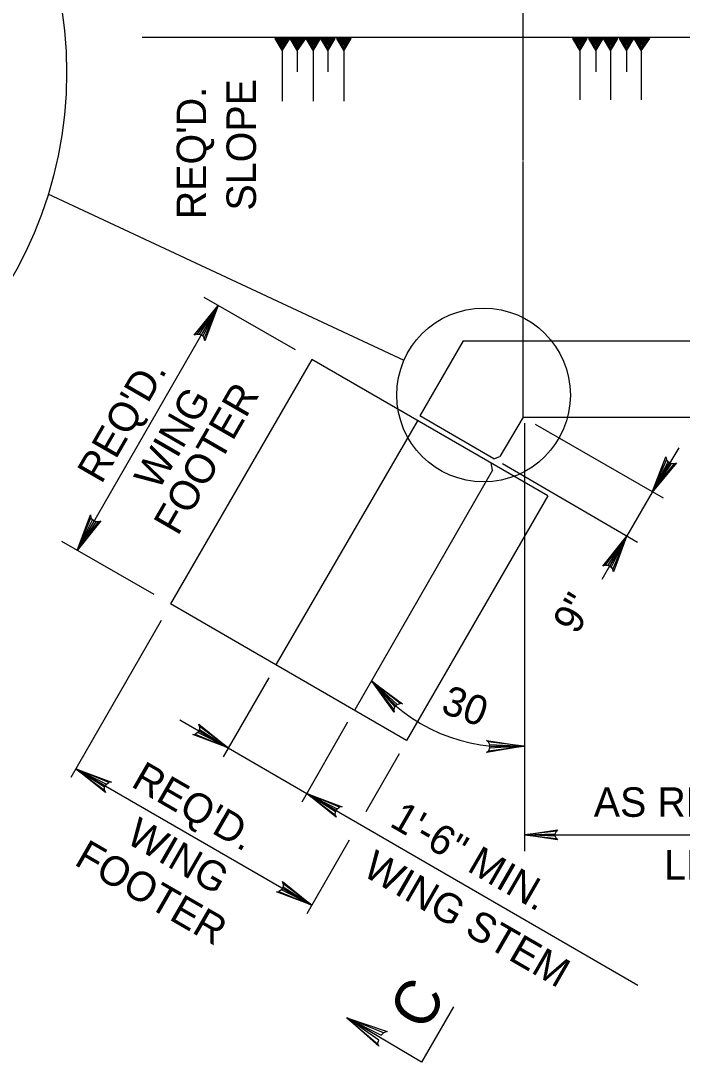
# Model space of a CAD drawing. Extents: x 639011 to 639866, y 298840 to 300028.
# Drawn here: x 639141.6 to 639208.9, y 299864.4 to 299970.3 of the extents above; entities that cross this region are included whole.
import ezdxf

# ---------------------------------------------------------------- set-up
doc = ezdxf.new("R2010")
doc.units = 0
doc.layers.add('2', color=7, linetype='Continuous')

msp = doc.modelspace()

# ---------------------------------------------------------------- linework, layer by layer
at = {"layer": '2'}
for p, q in [((639192.69, 299956.09), (639192.69, 299976.73)), ((639153.94, 299968.6), (639239.07, 299968.6)), ((639164.42, 299968.6), (639305.62, 299968.6)), ((639168.19, 299967.23), (639168.19, 299962.1)), ((639169.69, 299967.23), (639169.69, 299965.1)), ((639171.32, 299967.23), (639171.32, 299962.1)), ((639172.82, 299967.23), (639172.82, 299965.1)), ((639174.44, 299967.23), (639174.44, 299962.1)), ((639198.44, 299967.23), (639198.44, 299962.23)), ((639200.07, 299967.23), (639200.07, 299965.1)), ((639201.57, 299967.23), (639201.57, 299962.23)), ((639203.19, 299967.23), (639203.19, 299965.1)), ((639204.69, 299967.23), (639204.69, 299962.23)), ((639192.69, 299937.23), (639192.69, 299955.98)), ((639180.57, 299935.73), (639144.39, 299952.65)), ((639192.69, 299938.23), (639192.69, 299946.48)), ((639192.69, 299938.23), (639192.69, 299946.48)), ((639169.52, 299936.81), (639160.23, 299942.15)), ((639161.65, 299941.34), (639147.34, 299916.43)), ((639159.24, 299938.33), (639161.65, 299941.34)), ((639161.65, 299941.34), (639159.48, 299938.42)), ((639159.77, 299938.41), (639161.65, 299941.34)), ((639161.65, 299941.34), (639159.93, 299938.32)), ((639161.65, 299941.34), (639160.09, 299938.23)), ((639160.25, 299937.99), (639161.65, 299941.34)), ((639161.65, 299941.34), (639160.31, 299937.73)), ((639159.48, 299938.42), (639159.24, 299938.33)), ((639159.48, 299938.42), (639159.77, 299938.41)), ((639159.77, 299938.41), (639160.09, 299938.23)), ((639160.09, 299938.23), (639160.25, 299937.99)), ((639160.31, 299937.73), (639160.25, 299937.99)), ((639186.57, 299937.73), (639182.19, 299930.1)), ((639186.57, 299937.73), (639244.22, 299937.73)), ((639192.69, 299929.98), (639192.69, 299937.23)), ((639192.69, 299929.98), (639192.69, 299937.23)), ((639171.19, 299935.85), (639156.82, 299910.98)), ((639195.19, 299921.98), (639171.19, 299935.85)), ((639189.69, 299925.73), (639182.19, 299930.1)), ((639181.94, 299929.6), (639167.57, 299904.85)), ((639192.69, 299929.98), (639190.32, 299925.98)), ((639192.69, 299929.98), (639238.07, 299929.98)), ((639192.82, 299929.35), (639192.82, 299885.85)), ((639206.94, 299921.73), (639193.94, 299929.23)), ((639189.69, 299925.73), (639190.32, 299925.98)), ((639208.5, 299926.87), (639205.82, 299922.35)), ((639205.82, 299922.35), (639207.21, 299925.94)), ((639207.21, 299925.94), (639207.26, 299925.68)), ((639189.57, 299924.6), (639189.44, 299925.35)), ((639204.32, 299917.23), (639190.57, 299925.23)), ((639207.26, 299925.68), (639205.82, 299922.35)), ((639205.82, 299922.35), (639207.42, 299925.44)), ((639205.82, 299922.35), (639207.58, 299925.35)), ((639208.27, 299925.32), (639205.82, 299922.35)), ((639207.74, 299925.25), (639205.82, 299922.35)), ((639205.82, 299922.35), (639208.03, 299925.24)), ((639207.42, 299925.44), (639207.26, 299925.68)), ((639207.74, 299925.25), (639207.42, 299925.44)), ((639208.03, 299925.24), (639207.74, 299925.25)), ((639208.03, 299925.24), (639208.27, 299925.32)), ((639189.57, 299924.6), (639175.57, 299900.23)), ((639195.19, 299921.98), (639180.82, 299897.1)), ((639205.82, 299922.35), (639203.19, 299917.85)), ((639147.34, 299916.43), (639148.68, 299920.03)), ((639148.73, 299919.77), (639147.34, 299916.43)), ((639147.34, 299916.43), (639148.89, 299919.53)), ((639148.68, 299920.03), (639148.73, 299919.77)), ((639148.89, 299919.53), (639148.73, 299919.77)), ((639149.21, 299919.35), (639148.89, 299919.53)), ((639147.34, 299916.43), (639149.05, 299919.44)), ((639149.74, 299919.43), (639147.34, 299916.43)), ((639149.21, 299919.35), (639147.34, 299916.43)), ((639147.34, 299916.43), (639149.51, 299919.34)), ((639149.51, 299919.34), (639149.21, 299919.35)), ((639149.51, 299919.34), (639149.74, 299919.43)), ((639203.19, 299917.85), (639200.69, 299913.48)), ((639200.8, 299914.84), (639203.19, 299917.85)), ((639203.19, 299917.85), (639201.03, 299914.93)), ((639201.33, 299914.92), (639203.19, 299917.85)), ((639203.19, 299917.85), (639201.49, 299914.83)), ((639203.19, 299917.85), (639201.64, 299914.74)), ((639201.81, 299914.5), (639203.19, 299917.85)), ((639203.19, 299917.85), (639201.86, 299914.24)), ((639155.15, 299911.93), (639145.75, 299917.33)), ((639201.03, 299914.93), (639200.8, 299914.84)), ((639201.03, 299914.93), (639201.33, 299914.92)), ((639201.33, 299914.92), (639201.64, 299914.74)), ((639201.64, 299914.74), (639201.81, 299914.5)), ((639201.86, 299914.24), (639201.81, 299914.5)), ((639180.82, 299897.1), (639156.82, 299910.98)), ((639155.86, 299909.31), (639146.69, 299893.35)), ((639166.82, 299903.48), (639162.16, 299895.44)), ((639179.63, 299900.51), (639177.31, 299903.1)), ((639177.31, 299903.1), (639179.53, 299900.23)), ((639179.56, 299899.98), (639177.31, 299903.1)), ((639177.31, 299903.1), (639179.88, 299900.77)), ((639180.16, 299900.86), (639177.31, 299903.1)), ((639177.31, 299903.1), (639180.42, 299900.84)), ((639177.31, 299903.1), (639179.76, 299900.64)), ((639179.53, 299900.23), (639179.63, 299900.51)), ((639179.63, 299900.51), (639179.88, 299900.77)), ((639179.88, 299900.77), (639180.16, 299900.86)), ((639180.42, 299900.84), (639180.16, 299900.86)), ((639179.53, 299900.23), (639179.56, 299899.98)), ((639157.78, 299899.19), (639162.69, 299896.35)), ((639159.78, 299898.53), (639159.69, 299898.77)), ((639159.69, 299898.77), (639162.69, 299896.35)), ((639159.78, 299898.53), (639159.76, 299898.23)), ((639162.69, 299896.35), (639159.78, 299898.53)), ((639174.82, 299898.98), (639170.16, 299890.82)), ((639159.08, 299897.7), (639159.34, 299897.76)), ((639162.69, 299896.35), (639159.08, 299897.7)), ((639159.58, 299897.92), (639159.34, 299897.76)), ((639159.34, 299897.76), (639162.69, 299896.35)), ((639159.76, 299898.23), (639159.58, 299897.92)), ((639162.69, 299896.35), (639159.58, 299897.92)), ((639162.69, 299896.35), (639159.67, 299898.08)), ((639159.76, 299898.23), (639162.69, 299896.35)), ((639162.69, 299896.35), (639170.67, 299891.72)), ((639189.13, 299896.95), (639188.94, 299897.11)), ((639188.94, 299897.11), (639192.74, 299896.54)), ((639192.74, 299896.54), (639188.95, 299895.88)), ((639189.13, 299896.95), (639189.27, 299896.68)), ((639192.74, 299896.54), (639189.13, 299896.95)), ((639189.15, 299896.06), (639192.74, 299896.54)), ((639189.27, 299896.32), (639189.15, 299896.06)), ((639189.27, 299896.68), (639192.74, 299896.54)), ((639189.27, 299896.68), (639189.27, 299896.32)), ((639192.74, 299896.54), (639189.27, 299896.32)), ((639192.74, 299896.54), (639189.27, 299896.5)), ((639180.07, 299895.73), (639176.68, 299889.85)), ((639188.95, 299895.88), (639189.15, 299896.06)), ((639147.19, 299894.23), (639171.19, 299880.35)), ((639150.12, 299892.35), (639147.19, 299894.23)), ((639147.19, 299894.23), (639150.1, 299892.05)), ((639150.19, 299891.81), (639147.19, 299894.23)), ((639147.19, 299894.23), (639150.3, 299892.66)), ((639150.54, 299892.82), (639147.19, 299894.23)), ((639147.19, 299894.23), (639150.8, 299892.88)), ((639147.19, 299894.23), (639150.21, 299892.5)), ((639150.1, 299892.05), (639150.12, 299892.35)), ((639150.1, 299892.05), (639150.19, 299891.81)), ((639150.12, 299892.35), (639150.3, 299892.66)), ((639150.3, 299892.66), (639150.54, 299892.82)), ((639150.8, 299892.88), (639150.54, 299892.82)), ((639170.67, 299891.72), (639204.35, 299872.21)), ((639173.59, 299889.84), (639170.67, 299891.72)), ((639170.67, 299891.72), (639173.58, 299889.54)), ((639173.67, 299889.31), (639170.67, 299891.72)), ((639170.67, 299891.72), (639173.77, 299890.15)), ((639174.02, 299890.32), (639170.67, 299891.72)), ((639170.67, 299891.72), (639174.27, 299890.37)), ((639170.67, 299891.72), (639173.68, 299890)), ((639173.58, 299889.54), (639173.59, 299889.84)), ((639173.59, 299889.84), (639173.77, 299890.15)), ((639173.77, 299890.15), (639174.02, 299890.32)), ((639174.27, 299890.37), (639174.02, 299890.32)), ((639173.58, 299889.54), (639173.67, 299889.31)), ((639175, 299886.95), (639170.69, 299879.48)), ((639192.82, 299887.5), (639237.89, 299887.5)), ((639168.29, 299882.53), (639168.2, 299882.77)), ((639168.2, 299882.77), (639171.19, 299880.35)), ((639168.29, 299882.53), (639168.27, 299882.23)), ((639171.19, 299880.35), (639168.29, 299882.53)), ((639167.59, 299881.7), (639167.85, 299881.76)), ((639171.19, 299880.35), (639167.59, 299881.7)), ((639168.09, 299881.92), (639167.85, 299881.76)), ((639167.85, 299881.76), (639171.19, 299880.35)), ((639168.27, 299882.23), (639168.09, 299881.92)), ((639171.19, 299880.35), (639168.09, 299881.92)), ((639171.19, 299880.35), (639168.18, 299882.08)), ((639168.27, 299882.23), (639171.19, 299880.35)), ((639185.61, 299870.02), (639182.36, 299864.39)), ((639182.36, 299864.39), (639174.74, 299868.89))]:
    msp.add_line(p, q, dxfattribs=at)
for points in [[(639168.94, 299968.48), (639167.44, 299968.48), (639168.19, 299967.23)], [(639170.57, 299968.48), (639168.94, 299968.48), (639169.69, 299967.23)], [(639172.07, 299968.48), (639170.57, 299968.48), (639171.32, 299967.23)], [(639173.57, 299968.48), (639172.07, 299968.48), (639172.82, 299967.23)], [(639175.19, 299968.48), (639173.69, 299968.48), (639174.44, 299967.23)], [(639199.19, 299968.48), (639197.69, 299968.48), (639198.44, 299967.23)], [(639200.82, 299968.48), (639199.32, 299968.48), (639200.07, 299967.23)], [(639202.32, 299968.48), (639200.82, 299968.48), (639201.57, 299967.23)], [(639203.94, 299968.48), (639202.44, 299968.48), (639203.19, 299967.23)], [(639205.57, 299968.48), (639203.94, 299968.48), (639204.69, 299967.23)]]:
    msp.add_lwpolyline(points, close=True, dxfattribs=at)
for points in [[(639168.94, 299968.48), (639167.44, 299968.48), (639168.19, 299967.23), (639168.82, 299968.48), (639167.57, 299968.48), (639168.19, 299967.35), (639168.82, 299968.48), (639167.69, 299968.35), (639168.19, 299967.48), (639168.69, 299968.35), (639167.82, 299968.35), (639168.19, 299967.6), (639168.57, 299968.35), (639167.94, 299968.23), (639168.19, 299967.85), (639168.44, 299968.23), (639168.07, 299968.23), (639168.19, 299967.98), (639168.32, 299968.23), (639168.07, 299968.1), (639168.19, 299968.1), (639168.19, 299968.1)], [(639170.44, 299968.48), (639169.07, 299968.48), (639169.69, 299967.23), (639170.44, 299968.48), (639169.07, 299968.48), (639169.69, 299967.35), (639170.32, 299968.35), (639169.19, 299968.35), (639169.69, 299967.48), (639170.19, 299968.35), (639169.32, 299968.35), (639169.69, 299967.6), (639170.07, 299968.35), (639169.44, 299968.23), (639169.69, 299967.73), (639169.94, 299968.23), (639169.57, 299968.23), (639169.69, 299967.98), (639169.94, 299968.23), (639169.69, 299968.1), (639169.69, 299967.98), (639169.82, 299968.1)], [(639172.07, 299968.48), (639170.57, 299968.48), (639171.32, 299967.23), (639171.94, 299968.48), (639170.69, 299968.48), (639171.32, 299967.35), (639171.94, 299968.35), (639170.82, 299968.35), (639171.32, 299967.48), (639171.82, 299968.35), (639170.94, 299968.35), (639171.32, 299967.6), (639171.69, 299968.35), (639170.94, 299968.23), (639171.32, 299967.85), (639171.57, 299968.23), (639171.07, 299968.23), (639171.32, 299967.98), (639171.44, 299968.23), (639171.19, 299968.1), (639171.32, 299968.1), (639171.32, 299968.1)], [(639173.57, 299968.48), (639172.19, 299968.48), (639172.82, 299967.23), (639173.57, 299968.48), (639172.19, 299968.48), (639172.82, 299967.35), (639173.44, 299968.35), (639172.32, 299968.35), (639172.82, 299967.48), (639173.32, 299968.35), (639172.44, 299968.35), (639172.82, 299967.6), (639173.19, 299968.35), (639172.57, 299968.23), (639172.82, 299967.85), (639173.07, 299968.23), (639172.69, 299968.23), (639172.82, 299967.98), (639173.07, 299968.23), (639172.82, 299968.1), (639172.82, 299968.1), (639172.94, 299968.1)], [(639175.19, 299968.48), (639173.69, 299968.48), (639174.44, 299967.23), (639175.07, 299968.48), (639173.82, 299968.48), (639174.44, 299967.35), (639175.07, 299968.48), (639173.94, 299968.35), (639174.44, 299967.48), (639174.94, 299968.35), (639174.07, 299968.35), (639174.44, 299967.6), (639174.82, 299968.35), (639174.07, 299968.23), (639174.44, 299967.85), (639174.69, 299968.23), (639174.19, 299968.23), (639174.44, 299967.98), (639174.57, 299968.23), (639174.32, 299968.1), (639174.44, 299968.1), (639174.44, 299968.1)], [(639199.19, 299968.48), (639197.82, 299968.48), (639198.44, 299967.23), (639199.19, 299968.48), (639197.82, 299968.48), (639198.44, 299967.35), (639199.07, 299968.48), (639197.94, 299968.35), (639198.44, 299967.48), (639198.94, 299968.35), (639198.07, 299968.35), (639198.44, 299967.6), (639198.82, 299968.35), (639198.19, 299968.35), (639198.44, 299967.85), (639198.69, 299968.23), (639198.32, 299968.23), (639198.44, 299967.98), (639198.69, 299968.23), (639198.44, 299968.23), (639198.44, 299968.1), (639198.57, 299968.1)], [(639200.82, 299968.48), (639199.32, 299968.48), (639200.07, 299967.23), (639200.69, 299968.48), (639199.44, 299968.48), (639200.07, 299967.35), (639200.69, 299968.48), (639199.57, 299968.35), (639200.07, 299967.48), (639200.57, 299968.35), (639199.69, 299968.35), (639200.07, 299967.6), (639200.44, 299968.35), (639199.82, 299968.23), (639200.07, 299967.85), (639200.32, 299968.23), (639199.94, 299968.23), (639200.07, 299967.98), (639200.19, 299968.23), (639199.94, 299968.1), (639200.07, 299968.1), (639200.07, 299968.1)], [(639202.32, 299968.48), (639200.94, 299968.48), (639201.57, 299967.23), (639202.32, 299968.48), (639200.94, 299968.48), (639201.57, 299967.35), (639202.19, 299968.48), (639201.07, 299968.35), (639201.57, 299967.48), (639202.07, 299968.35), (639201.19, 299968.35), (639201.57, 299967.6), (639201.94, 299968.35), (639201.32, 299968.23), (639201.57, 299967.85), (639201.82, 299968.23), (639201.44, 299968.23), (639201.57, 299967.98), (639201.82, 299968.23), (639201.57, 299968.1), (639201.57, 299968.1), (639201.69, 299968.1)], [(639203.94, 299968.48), (639202.44, 299968.48), (639203.19, 299967.23), (639203.82, 299968.48), (639202.57, 299968.48), (639203.19, 299967.35), (639203.82, 299968.48), (639202.69, 299968.35), (639203.19, 299967.48), (639203.69, 299968.35), (639202.69, 299968.35), (639203.19, 299967.6), (639203.57, 299968.35), (639202.82, 299968.23), (639203.19, 299967.85), (639203.44, 299968.23), (639202.94, 299968.23), (639203.19, 299967.98), (639203.32, 299968.23), (639203.07, 299968.1), (639203.19, 299968.1), (639203.19, 299968.1)], [(639205.44, 299968.48), (639204.07, 299968.48), (639204.69, 299967.23), (639205.44, 299968.48), (639204.07, 299968.48), (639204.69, 299967.35), (639205.32, 299968.48), (639204.19, 299968.35), (639204.69, 299967.48), (639205.19, 299968.35), (639204.32, 299968.35), (639204.69, 299967.6), (639205.07, 299968.35), (639204.44, 299968.35), (639204.69, 299967.85), (639204.94, 299968.23), (639204.57, 299968.23), (639204.69, 299967.98), (639204.94, 299968.23), (639204.69, 299968.23), (639204.69, 299968.1), (639204.82, 299968.1)], [(639196.07, 299887.12), (639195.94, 299887.37), (639192.82, 299887.5), (639196.07, 299887.12), (639196.19, 299887), (639192.82, 299887.5), (639195.94, 299887.62), (639196.07, 299887.87), (639192.82, 299887.5), (639196.19, 299888), (639196.07, 299887.87)], [(639177.86, 299866.27), (639177.99, 299866.64), (639174.74, 299868.89), (639177.86, 299866.27), (639177.99, 299866.02), (639174.74, 299868.89), (639178.24, 299867.14), (639178.49, 299867.39), (639174.74, 299868.89), (639178.86, 299867.52), (639178.49, 299867.39)]]:
    msp.add_lwpolyline(points, dxfattribs=at)
for centre, radius in [((639104.3, 299965.01), 41.95), ((639188.66, 299932.23), 8.83)]:
    msp.add_circle(centre, radius, dxfattribs=at)
msp.add_arc((639191.07, 299914.04), 17.58, 218.4716, 275.4551, dxfattribs=at)

# ---------------------------------------------------------------- texts
for s, height, rotation, p in [('SLOPE', 3, 90, (639165.51, 299950.98)), ("REQ'D.", 3, 90, (639160.44, 299950.09)), ("REQ'D.", 3, 60.0025, (639149.79, 299923.09)), ('FOOTER', 3, 60.0025, (639157.56, 299917.82)), ('WING', 3, 60.0025, (639155.58, 299922.41)), ('9"', 3, 59.9975, (639198.14, 299907.76)), ('30', 3, 340, (639184.19, 299899.98)), ("REQ'D.", 3, 330.0025, (639152.69, 299892.49)), ('1\'-6" MIN.', 3, 330.0025, (639178.98, 299888.45)), ('WING', 3, 330.0025, (639152.13, 299886.8)), ('FOOTER', 3, 330.0025, (639146.91, 299884.53)), ('WING STEM', 3, 330.0025, (639176.19, 299883.47)), ('C', 4.5, 60.0159, (639182.74, 299867.39))]:
    msp.add_text(s, height=height, rotation=rotation, dxfattribs=at).set_placement(p)
for s, p in [('AS REQUIRED', (639199.86, 299889.34)), ('LENGTH', (639207.01, 299882.96))]:
    msp.add_text(s, height=3, dxfattribs=at).set_placement(p)

doc.saveas('drawing.dxf')
